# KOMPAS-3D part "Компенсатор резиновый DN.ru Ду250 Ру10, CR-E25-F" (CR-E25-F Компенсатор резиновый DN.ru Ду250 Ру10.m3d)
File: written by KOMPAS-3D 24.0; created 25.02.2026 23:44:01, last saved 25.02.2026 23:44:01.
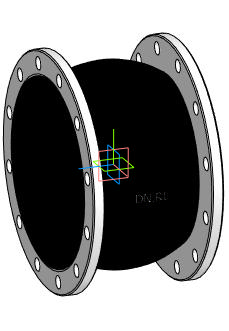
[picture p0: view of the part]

Document properties: Автор: DN.RU; Полное имя файла: D:\PROJECT CAD\DN.RU\...178(4)(ACTUALE). CR-E25-F Компенсатор резиновый DN.ru Ру10-16\DN250_PN10\CR-E25-F Компенсатор резиновый DN.ru Ду250 Ру10.m3d

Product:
- Body: Твердое тело2  | qty 1
    Масса: 65.782799
- Part/product: Компенсатор резиновый DN.ru Ду250 Ру10  | designation CR-E25-F
    Масса: 26.25
    Раздел спецификации: Прочие изделия
    Комментарий: D140-02169
    Примечание: D140-02169
    additional columns: Типовые

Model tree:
1. Твердое тело2  (labels: Твердое тело2)

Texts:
  CR-E25-F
